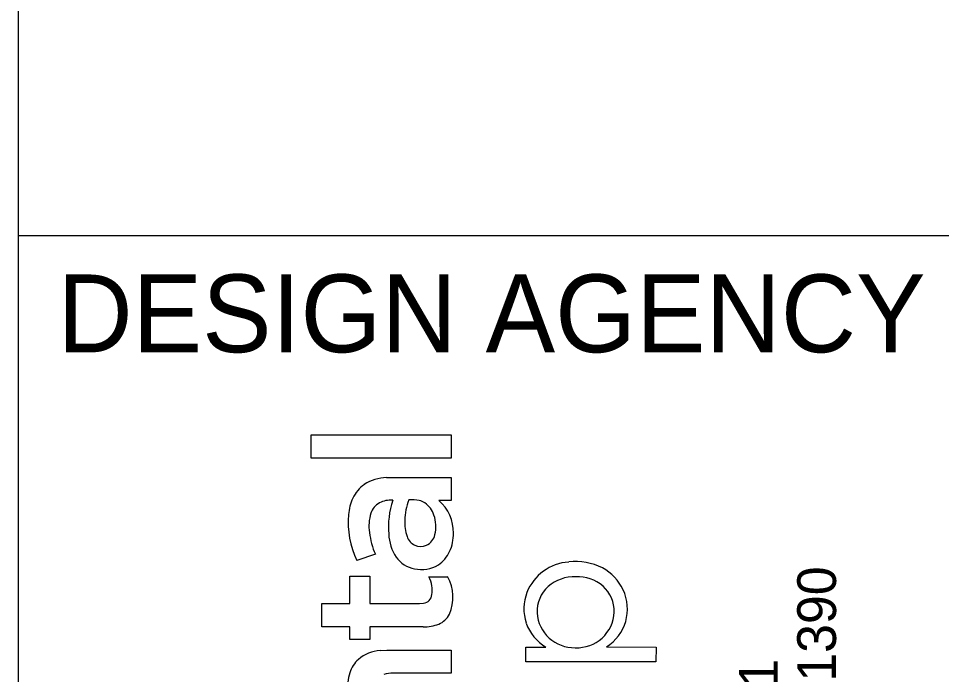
# Model space of a CAD drawing. Extents: x -0.4 to 34, y 0 to 22.
# Drawn here: x 32 to 33.185, y 3.936 to 4.779 of the extents above; entities that cross this region are included whole.
import ezdxf

# ---------------------------------------------------------------- set-up
doc = ezdxf.new("R2010")
doc.units = 0
doc.layers.add('SH_Border', color=7, linetype='Continuous')
doc.layers.add('SH_Data', color=7, linetype='Continuous')

msp = doc.modelspace()

# ---------------------------------------------------------------- linework, layer by layer
at = {"layer": 'SH_Border'}
for p, q in [((32, 0.5), (32, 21.5)), ((32, 4.5), (33.5, 4.5))]:
    msp.add_line(p, q, dxfattribs=at)
at = {"layer": 'SH_Data'}
for p, q in [((32.3756, 4.2141), (32.3756, 4.244)), ((32.3756, 4.244), (32.5557, 4.244)), ((32.5557, 4.244), (32.5557, 4.2141)), ((32.5557, 4.2141), (32.3756, 4.2141)), ((32.4727, 4.189), (32.5555, 4.1892)), ((32.5555, 4.1892), (32.5557, 4.1596)), ((32.5557, 4.1596), (32.5397, 4.1596)), ((32.4582, 4.0904), (32.4343, 4.0823)), ((32.4254, 4.027), (32.4255, 4.0621)), ((32.4255, 4.0621), (32.4511, 4.0621)), ((32.4511, 4.0621), (32.4512, 4.027)), ((32.527, 4.0616), (32.5511, 4.0616)), ((32.3896, 3.9972), (32.3896, 4.027)), ((32.3896, 4.027), (32.4254, 4.027)), ((32.4512, 4.027), (32.515, 4.027)), ((32.515, 4.027), (32.52, 4.0275)), ((32.4254, 3.9972), (32.3896, 3.9972)), ((32.4254, 3.9807), (32.4254, 3.9972)), ((32.5197, 3.9972), (32.4511, 3.9972)), ((32.4511, 3.9972), (32.4511, 3.9807)), ((32.4511, 3.9807), (32.4254, 3.9807)), ((32.6515, 3.9521), (32.6515, 3.9711)), ((32.6515, 3.9711), (32.6771, 3.9711)), ((32.7549, 3.9713), (32.8186, 3.9711)), ((32.8186, 3.9711), (32.8184, 3.9521)), ((32.4644, 3.9669), (32.4729, 3.9673)), ((32.4729, 3.9673), (32.5557, 3.9673)), ((32.5557, 3.9673), (32.5557, 3.9375)), ((32.8184, 3.9521), (32.6515, 3.9521)), ((32.5557, 3.9375), (32.4814, 3.9375))]:
    msp.add_line(p, q, dxfattribs=at)
msp.add_lwpolyline([(32.3756, 4.2141), (32.3756, 4.244), (32.5557, 4.244), (32.5557, 4.2141)], close=True, dxfattribs=at)
for points in [[(32.4727, 4.189), (32.5555, 4.1892), (32.5557, 4.1596)], [(32.5557, 4.1596), (32.5397, 4.1596)], [(32.4582, 4.0904), (32.4343, 4.0823)], [(32.5197, 3.9972), (32.4511, 3.9972), (32.4511, 3.9807), (32.4254, 3.9807), (32.4254, 3.9972), (32.3896, 3.9972), (32.3896, 4.027), (32.4254, 4.027), (32.4255, 4.0621), (32.4511, 4.0621), (32.4512, 4.027), (32.515, 4.027), (32.52, 4.0275)], [(32.527, 4.0616), (32.5511, 4.0616)], [(32.7549, 3.9713), (32.8186, 3.9711), (32.8184, 3.9521), (32.6515, 3.9521)], [(32.6515, 3.9521), (32.6515, 3.9711), (32.6771, 3.9711)], [(32.4644, 3.9669), (32.4729, 3.9673), (32.5557, 3.9673), (32.5557, 3.9375), (32.4814, 3.9375)]]:
    msp.add_lwpolyline(points, dxfattribs=at)
for centre, radius, start, end in [((32.4745, 4.1326), 0.0565, 91.8942, 122.6317), ((32.4745, 4.1326), 0.0565, 91.8942, 122.6317), ((32.4685, 4.1447), 0.043, 124.537, 155.6594), ((32.4685, 4.1447), 0.043, 124.537, 155.6594), ((32.4882, 4.1361), 0.0646, 155.9764, 175.3149), ((32.4882, 4.1361), 0.0646, 155.9764, 175.3149), ((32.4779, 4.1278), 0.0321, 85.3802, 116.6222), ((32.4779, 4.1278), 0.0321, 85.3802, 116.6222), ((32.5801, 4.1313), 0.0841, 159.8366, 178.0362), ((32.5801, 4.1313), 0.0841, 159.8366, 178.0362), ((32.5051, 4.1074), 0.053, 79.6696, 94.2322), ((32.5051, 4.1074), 0.053, 79.6696, 94.2322), ((32.4753, 4.1356), 0.024, 119.4252, 161.6629), ((32.4753, 4.1356), 0.024, 119.4252, 161.6629), ((32.5879, 4.1251), 0.1129, 162.0821, 184.5285), ((32.5879, 4.1251), 0.1129, 162.0821, 184.5285), ((32.5089, 4.1364), 0.0238, 56.8913, 76.2149), ((32.5089, 4.1364), 0.0238, 56.8913, 76.2149), ((32.5052, 4.1318), 0.0297, 17.5984, 55.7282), ((32.5052, 4.1318), 0.0297, 17.5984, 55.7282), ((32.5055, 4.1191), 0.0529, 358.0746, 49.762), ((32.5055, 4.1191), 0.0529, 358.0746, 49.762), ((32.5364, 4.1308), 0.113, 174.6101, 205.3899), ((32.5364, 4.1308), 0.113, 174.6101, 205.3899), ((32.5076, 4.1265), 0.0576, 163.1369, 188.1675), ((32.5076, 4.1265), 0.0576, 163.1369, 188.1675), ((32.4916, 4.1264), 0.0443, 345.9408, 18.9919), ((32.4916, 4.1264), 0.0443, 345.9408, 18.9919), ((32.5466, 4.1303), 0.0506, 175.5903, 199.8857), ((32.5466, 4.1303), 0.0506, 175.5903, 199.8857), ((32.5473, 4.1297), 0.0973, 186.7598, 203.7981), ((32.5473, 4.1297), 0.0973, 186.7598, 203.7981), ((32.5328, 4.1187), 0.0575, 182.5676, 213.7144), ((32.5328, 4.1187), 0.0575, 182.5676, 213.7144), ((32.5164, 4.1189), 0.0184, 198.2844, 293.3081), ((32.5164, 4.1189), 0.0184, 198.2844, 293.3081), ((32.5152, 4.1199), 0.0199, 295.2883, 347.4639), ((32.5152, 4.1199), 0.0199, 295.2883, 347.4639), ((32.5019, 4.1168), 0.0566, 336.016, 0.5951), ((32.5019, 4.1168), 0.0566, 336.016, 0.5951), ((32.5175, 4.1097), 0.0394, 303.4436, 336.18), ((32.5175, 4.1097), 0.0394, 303.4436, 336.18), ((32.5149, 4.1078), 0.0366, 215.0668, 259.8133), ((32.5149, 4.1078), 0.0366, 215.0668, 259.8133), ((32.7108, 4.0182), 0.0624, 93.9866, 158.3119), ((32.7108, 4.0182), 0.0624, 93.9866, 158.3119), ((32.7156, 4.0065), 0.0746, 62.6889, 97.0135), ((32.7156, 4.0065), 0.0746, 62.6889, 97.0135), ((32.5175, 4.1131), 0.0423, 257.5256, 300.882), ((32.5175, 4.1131), 0.0423, 257.5256, 300.882), ((32.7212, 4.0191), 0.0608, 25.0657, 61.9602), ((32.7212, 4.0191), 0.0608, 25.0657, 61.9602), ((32.4863, 4.042), 0.0452, 10.1545, 25.723), ((32.4863, 4.042), 0.0452, 10.1545, 25.723), ((32.503, 4.0351), 0.0549, 336.589, 28.8991), ((32.503, 4.0351), 0.0549, 336.589, 28.8991), ((32.7138, 4.0102), 0.0513, 87.8965, 131.1812), ((32.7138, 4.0102), 0.0513, 87.8965, 131.1812), ((32.7175, 4.0102), 0.0513, 49.9089, 92.0363), ((32.7175, 4.0102), 0.0513, 49.9089, 92.0363), ((32.4957, 4.0436), 0.0356, 351.914, 10.2059), ((32.4957, 4.0436), 0.0356, 351.914, 10.2059), ((32.7092, 4.0167), 0.0434, 132.3289, 182.0949), ((32.7092, 4.0167), 0.0434, 132.3289, 182.0949), ((32.7215, 4.0173), 0.0433, 358.0487, 47.9447), ((32.7215, 4.0173), 0.0433, 358.0487, 47.9447), ((32.7245, 4.02), 0.0574, 301.9776, 25.6418), ((32.7245, 4.02), 0.0574, 301.9776, 25.6418), ((32.5184, 4.04), 0.0126, 277.6142, 353.7918), ((32.5184, 4.04), 0.0126, 277.6142, 353.7918), ((32.707, 4.0202), 0.0581, 158.656, 198.171), ((32.707, 4.0202), 0.0581, 158.656, 198.171), ((32.5291, 4.0261), 0.0275, 292.6889, 332.0598), ((32.5291, 4.0261), 0.0275, 292.6889, 332.0598), ((32.7135, 4.0181), 0.0478, 183.5974, 271.7045), ((32.7135, 4.0181), 0.0478, 183.5974, 271.7045), ((32.7172, 4.018), 0.0477, 267.3149, 357.4019), ((32.7172, 4.018), 0.0477, 267.3149, 357.4019), ((32.5209, 4.0486), 0.0514, 268.6727, 291.5235), ((32.5209, 4.0486), 0.0514, 268.6727, 291.5235), ((32.7103, 4.0243), 0.0627, 200.8399, 238.0162), ((32.7103, 4.0243), 0.0627, 200.8399, 238.0162), ((32.4687, 3.9172), 0.0499, 94.9706, 130.2248), ((32.4687, 3.9172), 0.0499, 94.9706, 130.2248), ((32.4635, 3.9255), 0.0402, 132.2238, 161.6823), ((32.4635, 3.9255), 0.0402, 132.2238, 161.6823), ((32.4787, 3.9211), 0.056, 162.274, 187.7917), ((32.4787, 3.9211), 0.056, 162.274, 187.7917), ((32.4811, 3.8915), 0.046, 89.6051, 105.3303), ((32.4811, 3.8915), 0.046, 89.6051, 105.3303)]:
    msp.add_arc(centre, radius, start, end, dxfattribs=at)

# ---------------------------------------------------------------- texts
msp.add_text('DESIGN AGENCY', height=0.1, dxfattribs=at).set_placement((32.05, 4.35))
for s, p in [('800.835.1390', (33.0497, 3.6671)), ('450 GRANT ST., AKRON, OH  44311', (32.9749, 2.8374))]:
    msp.add_text(s, height=0.049846, rotation=90, dxfattribs=at).set_placement(p)

doc.saveas('drawing.dxf')
